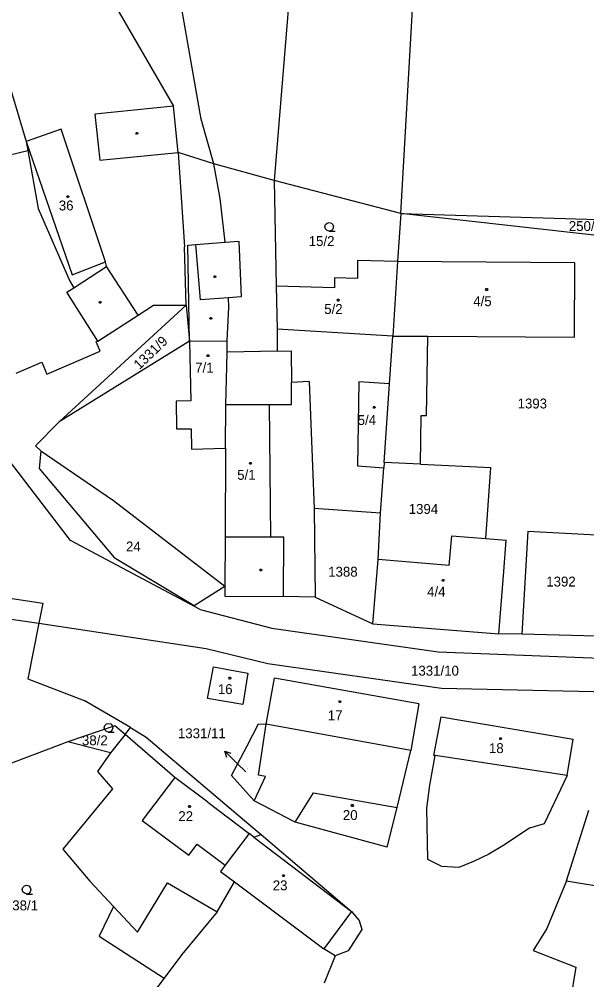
# Model space of a CAD drawing. Extents: x -852001 to -842497, y -1063614 to -1052182.
# Drawn here: x -844541.5 to -844444, y -1061526.1 to -1061361.2 of the extents above; entities that cross this region are included whole.
import ezdxf

# ---------------------------------------------------------------- set-up
doc = ezdxf.new("R2010")
doc.units = 0
for name, color, linetype in [('Default', 7, 'Continuous'), ('KN_HRANICE', 7, 'Continuous'), ('KN_KULTURY', 7, 'Continuous'), ('KN_PARCELY', 7, 'Continuous'), ('KN_SLUCKY', 7, 'Continuous')]:
    doc.layers.add(name, color=color, linetype=linetype)

# ---------------------------------------------------------------- blocks, each defined once
blk = doc.blocks.new('304')
at = {"layer": 'Default'}
blk.add_lwpolyline([(0, 0), (-0.38, 0.1), (-0.65, 0.37), (-0.75, 0.74), (-0.65, 1.11), (-0.38, 1.38), (-0.01, 1.48), (0.36, 1.38), (0.63, 1.11), (0.73, 0.73), (0.63, 0.35), (0.36, 0.08), (-0.02, -0.02), (0.98, -0.02)], dxfattribs=at)
blk = doc.blocks.new('10292')
at = {"layer": 'Default'}
blk.add_line((0, 3), (0, 0), dxfattribs=at)
blk.add_lwpolyline([(-0.5, 2), (0, 3), (0.5, 2)], dxfattribs=at)
blk = doc.blocks.new('402')
at = {"layer": 'Default'}
blk.add_lwpolyline([(0.09, 0.15), (0.18, 0), (0.09, -0.15), (-0.09, -0.15), (-0.18, 0), (-0.09, 0.15), (0.09, 0.15)], dxfattribs=at)

msp = doc.modelspace()

# ---------------------------------------------------------------- linework, layer by layer
at = {"layer": 'KN_HRANICE'}
for p, q in [((-844491.42, -1061312.67), (-844497.75, -1061388.86)), ((-844475.97, -1061394.54), (-844471.31, -1061313.26)), ((-844527.05, -1061355.32), (-844515.02, -1061376.12)), ((-844510.28, -1061378.35), (-844513.95, -1061357.42)), ((-844543.93, -1061370.06), (-844540.35, -1061382.16)), ((-844514.22, -1061384.06), (-844515.02, -1061376.12)), ((-844508.11, -1061386.03), (-844510.28, -1061378.35)), ((-844540.35, -1061382.16), (-844540.07, -1061383.72)), ((-844558.34, -1061388.2), (-844540.07, -1061383.72)), ((-844540.07, -1061383.72), (-844538.28, -1061393.67)), ((-844514.22, -1061384.06), (-844513.12, -1061400.25)), ((-844508.11, -1061386.03), (-844514.22, -1061384.06)), ((-844507, -1061391.95), (-844508.11, -1061386.03)), ((-844497.75, -1061388.86), (-844508.11, -1061386.03)), ((-844475.97, -1061394.54), (-844497.75, -1061388.86)), ((-844497.75, -1061388.86), (-844497.39, -1061407.02)), ((-844506.18, -1061399.48), (-844507, -1061391.95)), ((-844538.28, -1061393.67), (-844532.86, -1061406.15)), ((-844475.97, -1061394.54), (-844476.56, -1061402.81)), ((-844475.97, -1061394.54), (-844437.76, -1061395.7)), ((-844437.56, -1061398.83), (-844475.97, -1061394.54)), ((-844512.87, -1061410.29), (-844513.12, -1061400.25)), ((-844506.18, -1061399.48), (-844503.8, -1061399.32)), ((-844503.8, -1061399.32), (-844503.38, -1061408.87)), ((-844476.56, -1061402.81), (-844483.45, -1061402.59)), ((-844483.45, -1061402.59), (-844483.45, -1061405.7)), ((-844476.56, -1061402.81), (-844477.34, -1061415.58)), ((-844446.1, -1061402.99), (-844476.56, -1061402.81)), ((-844446.18, -1061415.77), (-844446.1, -1061402.99)), ((-844532.86, -1061406.15), (-844532.13, -1061407.28)), ((-844483.45, -1061405.7), (-844487.36, -1061405.61)), ((-844487.36, -1061405.61), (-844487.36, -1061407.3)), ((-844533.34, -1061408.07), (-844532.13, -1061407.28)), ((-844528.02, -1061416.46), (-844533.34, -1061408.07)), ((-844487.36, -1061407.3), (-844497.39, -1061407.02)), ((-844497.39, -1061407.02), (-844497.24, -1061414.43)), ((-844512.87, -1061410.29), (-844534.65, -1061430.32)), ((-844521.11, -1061411.99), (-844518.49, -1061410.26)), ((-844518.49, -1061410.26), (-844512.87, -1061410.29)), ((-844512.87, -1061410.29), (-844512.27, -1061416.48)), ((-844503.38, -1061408.87), (-844505.58, -1061409.03)), ((-844505.54, -1061410.63), (-844505.58, -1061409.03)), ((-844505.82, -1061416.42), (-844505.54, -1061410.63)), ((-844528.02, -1061416.46), (-844521.11, -1061411.99)), ((-844497.24, -1061414.43), (-844497.21, -1061418.2)), ((-844512.27, -1061416.48), (-844534.65, -1061430.32)), ((-844528.29, -1061416.58), (-844528.02, -1061416.46)), ((-844527.6, -1061418.16), (-844528.29, -1061416.58)), ((-844505.84, -1061418.35), (-844505.82, -1061416.42)), ((-844477.91, -1061423.8), (-844477.34, -1061415.58)), ((-844477.34, -1061415.58), (-844471.33, -1061415.62)), ((-844471.33, -1061415.62), (-844446.18, -1061415.77)), ((-844536.76, -1061422.14), (-844527.6, -1061418.16)), ((-844505.86, -1061420.82), (-844505.84, -1061418.35)), ((-844497.21, -1061418.2), (-844494.81, -1061418.12)), ((-844494.81, -1061418.12), (-844494.74, -1061423.55)), ((-844542.06, -1061421.97), (-844537.66, -1061420.06)), ((-844537.66, -1061420.06), (-844536.76, -1061422.14)), ((-844506.07, -1061427.33), (-844505.86, -1061420.82)), ((-844491.72, -1061423.39), (-844494.74, -1061423.55)), ((-844491.72, -1061423.39), (-844490.87, -1061445.21)), ((-844483.19, -1061423.43), (-844483.4, -1061437.88)), ((-844477.91, -1061423.8), (-844483.19, -1061423.43)), ((-844478.86, -1061437.32), (-844477.91, -1061423.8)), ((-844506.1, -1061434.82), (-844506.07, -1061427.33)), ((-844534.65, -1061430.32), (-844538.76, -1061434.44)), ((-844538.76, -1061434.44), (-844537.81, -1061435.32)), ((-844506.1, -1061434.82), (-844506.16, -1061450.12)), ((-844537.81, -1061435.32), (-844538.1, -1061438.35)), ((-844537.81, -1061435.32), (-844525.34, -1061443.83)), ((-844538.1, -1061438.35), (-844525.21, -1061453.61)), ((-844483.4, -1061437.88), (-844478.92, -1061438.19)), ((-844479.46, -1061446.01), (-844478.92, -1061438.19)), ((-844478.86, -1061437.32), (-844478.92, -1061438.19)), ((-844472.62, -1061437.6), (-844478.86, -1061437.32)), ((-844472.62, -1061437.6), (-844460.54, -1061438.15)), ((-844461.37, -1061450.37), (-844460.54, -1061438.15)), ((-844525.34, -1061443.83), (-844506.19, -1061458.53)), ((-844479.46, -1061446.01), (-844490.87, -1061445.21)), ((-844490.87, -1061445.21), (-844490.69, -1061460.43)), ((-844479.88, -1061453.98), (-844479.46, -1061446.01)), ((-844467.66, -1061454.96), (-844467.22, -1061449.89)), ((-844467.22, -1061449.89), (-844461.37, -1061450.37)), ((-844454.2, -1061449.07), (-844455.23, -1061466.77)), ((-844454.2, -1061449.07), (-844438.29, -1061449.97)), ((-844506.16, -1061450.12), (-844506.19, -1061458.53)), ((-844461.37, -1061450.37), (-844457.92, -1061450.65)), ((-844458.3, -1061456.01), (-844457.92, -1061450.65)), ((-844525.21, -1061453.61), (-844511.48, -1061461.86)), ((-844480.79, -1061464.98), (-844479.88, -1061453.98)), ((-844467.66, -1061454.96), (-844479.88, -1061453.98)), ((-844459.17, -1061466.7), (-844458.3, -1061456.01)), ((-844511.48, -1061461.86), (-844506.19, -1061458.53)), ((-844506.19, -1061458.53), (-844506.2, -1061460.27)), ((-844544.65, -1061460.34), (-844537.49, -1061461.47)), ((-844506.2, -1061460.27), (-844496.12, -1061460.31)), ((-844490.69, -1061460.43), (-844496.12, -1061460.31)), ((-844490.69, -1061460.43), (-844480.79, -1061464.98)), ((-844537.49, -1061461.47), (-844538.17, -1061464.9)), ((-844538.17, -1061464.9), (-844540.06, -1061474.46)), ((-844480.79, -1061464.98), (-844459.17, -1061466.7)), ((-844455.23, -1061466.77), (-844459.17, -1061466.7)), ((-844439.9, -1061467.16), (-844455.23, -1061466.77)), ((-844509.17, -1061477.83), (-844508.18, -1061472.36)), ((-844508.18, -1061472.36), (-844502.29, -1061473.49)), ((-844540.06, -1061474.46), (-844530.36, -1061478.14)), ((-844502.29, -1061473.49), (-844503.13, -1061478.82)), ((-844499.1, -1061482.2), (-844497.69, -1061474.31)), ((-844472.91, -1061478.73), (-844497.69, -1061474.31)), ((-844503.13, -1061478.82), (-844509.17, -1061477.83)), ((-844522.43, -1061482.82), (-844530.36, -1061478.14)), ((-844472.91, -1061478.73), (-844474.24, -1061486.74)), ((-844470.33, -1061487.58), (-844469.04, -1061480.99)), ((-844469.04, -1061480.99), (-844446.4, -1061484.8)), ((-844525.13, -1061482.52), (-844533.17, -1061485.27)), ((-844523.35, -1061484.01), (-844525.13, -1061482.52)), ((-844523.35, -1061484.01), (-844522.43, -1061482.82)), ((-844522.43, -1061482.82), (-844519.71, -1061484.45)), ((-844500.45, -1061491), (-844499.1, -1061482.2)), ((-844523.35, -1061484.01), (-844525.84, -1061487.14)), ((-844519.71, -1061484.45), (-844501.32, -1061500.02)), ((-844533.17, -1061485.27), (-844552.79, -1061492.69)), ((-844525.84, -1061487.14), (-844533.17, -1061485.27)), ((-844447.44, -1061491.04), (-844446.4, -1061484.8)), ((-844525.84, -1061487.14), (-844528.09, -1061490.36)), ((-844476.64, -1061496.54), (-844474.24, -1061486.74)), ((-844471.01, -1061492.7), (-844470.08, -1061487.62)), ((-844470.08, -1061487.62), (-844470.33, -1061487.58)), ((-844528.09, -1061490.36), (-844525.48, -1061493.33)), ((-844499.23, -1061491.2), (-844500.45, -1061491)), ((-844447.44, -1061491.04), (-844451.38, -1061499.36)), ((-844501.2, -1061495.38), (-844499.23, -1061491.2)), ((-844471.54, -1061496.63), (-844471.01, -1061492.7)), ((-844525.48, -1061493.33), (-844534.02, -1061503.71)), ((-844494.12, -1061499.03), (-844490.99, -1061494.04)), ((-844490.99, -1061494.04), (-844476.64, -1061496.54)), ((-844494.12, -1061499.03), (-844501.2, -1061495.38)), ((-844478.31, -1061503.35), (-844476.64, -1061496.54)), ((-844471.35, -1061505.46), (-844471.54, -1061496.63)), ((-844447.53, -1061509.13), (-844443.69, -1061496.99)), ((-844478.31, -1061503.35), (-844494.12, -1061499.03)), ((-844451.38, -1061499.36), (-844453.89, -1061500.11)), ((-844502.06, -1061501.02), (-844506.15, -1061506.42)), ((-844501.23, -1061501.65), (-844502.06, -1061501.02)), ((-844501.32, -1061500.02), (-844499.99, -1061501.15)), ((-844453.89, -1061500.11), (-844458.45, -1061503.11)), ((-844501.23, -1061501.65), (-844499.99, -1061501.15)), ((-844499.99, -1061501.15), (-844484.46, -1061514.39)), ((-844534.02, -1061503.71), (-844529.4, -1061509.21)), ((-844458.45, -1061503.11), (-844460.89, -1061504.52)), ((-844468.92, -1061506.65), (-844471.35, -1061505.46)), ((-844463.48, -1061505.8), (-844466.04, -1061506.84)), ((-844460.89, -1061504.52), (-844463.48, -1061505.8)), ((-844506.15, -1061506.42), (-844506.96, -1061507.5)), ((-844506.96, -1061507.5), (-844504.54, -1061509.31)), ((-844466.04, -1061506.84), (-844468.92, -1061506.65)), ((-844529.4, -1061509.21), (-844525.36, -1061513.51)), ((-844447.53, -1061509.13), (-844450.91, -1061517.31)), ((-844447.53, -1061509.13), (-844425.81, -1061512.7)), ((-844507.51, -1061514.42), (-844504.54, -1061509.31)), ((-844525.36, -1061513.51), (-844527.77, -1061518.6)), ((-844507.51, -1061514.42), (-844513.59, -1061521.76)), ((-844484.46, -1061514.39), (-844483.12, -1061515.92)), ((-844482.71, -1061517.5), (-844485.03, -1061521.15)), ((-844483.12, -1061515.92), (-844482.71, -1061517.5)), ((-844450.91, -1061517.31), (-844453.26, -1061521.11)), ((-844527.77, -1061518.6), (-844516.66, -1061525.83)), ((-844513.59, -1061521.76), (-844516.66, -1061525.83)), ((-844487.27, -1061521.98), (-844489.14, -1061526.71)), ((-844485.03, -1061521.15), (-844487.27, -1061521.98)), ((-844453.26, -1061521.11), (-844445.93, -1061523.92)), ((-844445.93, -1061523.92), (-844447.49, -1061533.39)), ((-844516.66, -1061525.83), (-844519.11, -1061529.08))]:
    msp.add_line(p, q, dxfattribs=at)
msp.add_lwpolyline([(-844501.2, -1061495.38), (-844505.07, -1061491.05), (-844502.36, -1061485.93), (-844500.43, -1061482.14), (-844499.1, -1061482.2)], dxfattribs=at)
at = {"layer": 'KN_PARCELY'}
msp.add_line((-844502.62, -1061490.42), (-844504.08, -1061488.98), dxfattribs=at)
at = {"layer": 'KN_SLUCKY'}
for p, q in [((-844515.02, -1061376.12), (-844528.52, -1061377.48)), ((-844528.52, -1061377.48), (-844527.69, -1061385.41)), ((-844534.32, -1061380.05), (-844540.35, -1061382.16)), ((-844526.69, -1061402.86), (-844534.32, -1061380.05)), ((-844540.35, -1061382.16), (-844532.45, -1061405.06)), ((-844527.69, -1061385.41), (-844514.22, -1061384.06)), ((-844512.59, -1061399.96), (-844511.22, -1061399.86)), ((-844512.27, -1061416.48), (-844512.59, -1061399.96)), ((-844511.22, -1061399.86), (-844506.18, -1061399.48)), ((-844510.4, -1061409.39), (-844511.22, -1061399.86)), ((-844532.45, -1061405.06), (-844526.69, -1061402.86)), ((-844532.13, -1061407.28), (-844526.55, -1061403.62)), ((-844526.55, -1061403.62), (-844526.69, -1061402.86)), ((-844521.11, -1061411.99), (-844526.55, -1061403.62)), ((-844505.58, -1061409.03), (-844510.4, -1061409.39)), ((-844477.34, -1061415.58), (-844497.24, -1061414.43)), ((-844532.72, -1061450.71), (-844558.62, -1061416.89)), ((-844512.27, -1061416.48), (-844505.82, -1061416.42)), ((-844512.27, -1061416.48), (-844512.08, -1061426.69)), ((-844471.57, -1061429.24), (-844471.33, -1061415.62)), ((-844497.21, -1061418.2), (-844505.84, -1061418.35)), ((-844494.78, -1061427.32), (-844494.74, -1061423.55)), ((-844512.08, -1061426.69), (-844514.58, -1061426.74)), ((-844514.58, -1061426.74), (-844514.49, -1061431.54)), ((-844506.07, -1061427.33), (-844498.54, -1061427.32)), ((-844498.54, -1061427.32), (-844494.78, -1061427.32)), ((-844498.31, -1061450.11), (-844498.54, -1061427.32)), ((-844472.62, -1061437.6), (-844472.47, -1061429.23)), ((-844472.47, -1061429.23), (-844471.57, -1061429.24)), ((-844514.49, -1061431.54), (-844511.99, -1061431.5)), ((-844511.99, -1061431.5), (-844511.92, -1061435)), ((-844511.92, -1061435), (-844506.1, -1061434.82)), ((-844510.47, -1061462.54), (-844532.72, -1061450.71)), ((-844498.31, -1061450.11), (-844506.16, -1061450.12)), ((-844496.08, -1061450.13), (-844498.31, -1061450.11)), ((-844496.12, -1061460.31), (-844496.08, -1061450.13)), ((-844558.37, -1061461.86), (-844538.17, -1061464.9)), ((-844510.47, -1061462.54), (-844498.15, -1061465.73)), ((-844538.17, -1061464.9), (-844509.4, -1061469.22)), ((-844498.15, -1061465.73), (-844469.55, -1061469.78)), ((-844509.4, -1061469.22), (-844498.84, -1061471.8)), ((-844469.55, -1061469.78), (-844431.61, -1061471.3)), ((-844498.84, -1061471.8), (-844468.98, -1061476.02)), ((-844468.98, -1061476.02), (-844432.78, -1061476.81)), ((-844474.24, -1061486.74), (-844499.1, -1061482.2)), ((-844514.78, -1061491.36), (-844523.35, -1061484.01)), ((-844447.44, -1061491.04), (-844470.08, -1061487.62)), ((-844514.78, -1061491.36), (-844520.39, -1061498.74)), ((-844509.14, -1061495.64), (-844514.78, -1061491.36)), ((-844509.14, -1061495.64), (-844502.06, -1061501.02)), ((-844520.39, -1061498.74), (-844512.39, -1061504.74)), ((-844501.23, -1061501.65), (-844484.46, -1061514.39)), ((-844512.39, -1061504.74), (-844510.95, -1061502.82)), ((-844510.95, -1061502.82), (-844506.15, -1061506.42)), ((-844521.2, -1061517.94), (-844516.05, -1061509.47)), ((-844516.05, -1061509.47), (-844507.51, -1061514.42)), ((-844504.54, -1061509.31), (-844489.21, -1061520.82)), ((-844525.36, -1061513.51), (-844521.2, -1061517.94)), ((-844484.46, -1061514.39), (-844489.21, -1061520.82)), ((-844487.27, -1061521.98), (-844489.21, -1061520.82))]:
    msp.add_line(p, q, dxfattribs=at)

# ---------------------------------------------------------------- block references
at = {"layer": 'KN_KULTURY'}
for name, p in [('402', (-844521.32, -1061380.76)), ('402', (-844533.18, -1061391.64)), ('304', (-844488.27, -1061397.57)), ('402', (-844507.92, -1061405.37)), ('402', (-844461.25, -1061407.59)), ('402', (-844527.64, -1061409.81)), ('402', (-844486.73, -1061409.43)), ('402', (-844508.62, -1061412.53)), ('402', (-844509.11, -1061418.94)), ('402', (-844480.56, -1061427.82)), ('402', (-844501.82, -1061437.46)), ('402', (-844500.03, -1061455.74)), ('402', (-844468.72, -1061457.55)), ('402', (-844505.35, -1061474.33)), ('402', (-844486.45, -1061478.37)), ('304', (-844526.18, -1061483.57)), ('402', (-844458.86, -1061484.72)), ('402', (-844484.32, -1061496.19)), ('402', (-844512.27, -1061496.36)), ('402', (-844496.13, -1061508.25)), ('304', (-844540.25, -1061511.37))]:
    msp.add_blockref(name, p, dxfattribs=at)
at = {"layer": 'KN_PARCELY', "rotation": 45.492849}
msp.add_blockref('10292', (-844504.08, -1061488.98), dxfattribs=at)

# ---------------------------------------------------------------- texts
at = {"layer": 'KN_PARCELY'}
for s, height, p in [('36', 1.7, (-844534.73, -1061394.02)), ('250/3', 1.7, (-844447.13, -1061397.55)), ('15/2', 1.7, (-844491.81, -1061400.13)), ('5/2', 1.7, (-844489.14, -1061411.79)), ('4/5', 1.7, (-844463.55, -1061410.46)), ('7/1', 1.7, (-844511.31, -1061421.86)), ('1393', 1.7, (-844455.93, -1061428.02)), ('5/4', 1.7, (-844483.4, -1061430.86)), ('5/1', 1.7, (-844504.09, -1061440.27)), ('1394', 1.7, (-844474.63, -1061446.12)), ('24', 1.7, (-844523.19, -1061452.57)), ('1388', 1.7, (-844488.46, -1061456.9)), ('1392', 1.7, (-844451.01, -1061458.59)), ('4/4', 1.7, (-844471.47, -1061460.32)), ('1331/10', 1.7, (-844474.23, -1061473.89)), ('16', 1.7, (-844507.41, -1061477.06)), ('17', 1.7, (-844488.53, -1061481.56)), ('1331/11', 1.7, (-844514.27, -1061484.64)), ('38/2', 1.7, (-844530.75, -1061485.85)), ('18', 1.7, (-844460.85, -1061487.19)), ('1331/11', 0.1, (-844502.51, -1061489.99)), ('22', 1.7, (-844514.2, -1061498.87)), ('20', 1.7, (-844485.94, -1061498.68)), ('23', 1.7, (-844497.98, -1061510.75)), ('38/1', 1.7, (-844542.72, -1061514.19))]:
    msp.add_text(s, height=height, dxfattribs=at).set_placement(p)
msp.add_text('1331/9', height=1.7, rotation=43.717, dxfattribs=at).set_placement((-844520.9, -1061421.46))

doc.saveas('drawing.dxf')
